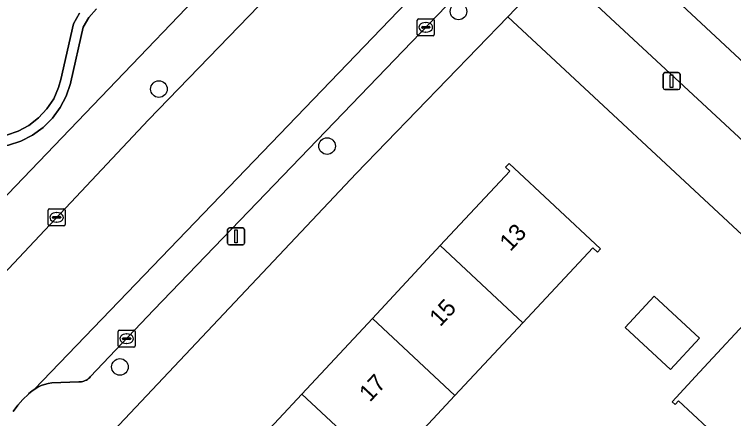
# Model space of a CAD drawing. Extents: x 159217 to 160349, y 381246 to 382172.
# Drawn here: x 159844.03 to 159886.39, y 381722 to 381745.8 of the extents above; entities that cross this region are included whole.
import ezdxf

# ---------------------------------------------------------------- set-up
doc = ezdxf.new("R2010")
doc.units = 0
for name, color, linetype in [('IMGEO_Boom', 7, 'Continuous'), ('IMGEO_Erf', 7, 'Continuous'), ('IMGEO_Groenvoorziening', 7, 'Continuous'), ('IMGEO_Haag', 7, 'Continuous'), ('IMGEO_Kolk', 7, 'Continuous'), ('IMGEO_Lichtmast', 7, 'Continuous'), ('IMGEO_Pand', 7, 'Continuous'), ('IMGEO_Pand_nummerreeks', 7, 'Continuous'), ('IMGEO_Parkeervlak_gesloten', 7, 'Continuous'), ('IMGEO_Rijbaan_lokaal_gesloten', 7, 'Continuous'), ('IMGEO_Voetpad_open', 7, 'Continuous')]:
    doc.layers.add(name, color=color, linetype=linetype)

msp = doc.modelspace()

# ---------------------------------------------------------------- linework, layer by layer
at = {"layer": 'IMGEO_Boom'}
for centre in [(159870.186, 381745.974), (159852.541, 381741.401), (159862.445, 381738.047), (159850.247, 381725.043)]:
    msp.add_circle(centre, 0.489, dxfattribs=at)
at = {"layer": 'IMGEO_Erf'}
for points in [[(159887.855, 381742.638), (159888.124, 381742.386), (159887.875, 381742.121), (159882.491, 381747.139), (159882.714, 381747.377), (159882.896, 381747.203), (159885.503, 381750), (159886.735, 381751.321), (159890.819, 381755.704), (159894.904, 381760.086), (159898.988, 381764.468), (159903.036, 381768.81), (159902.814, 381769.017), (159903.042, 381769.261), (159908.377, 381764.292), (159908.178, 381764.077), (159907.97, 381764.272), (159903.881, 381759.875), (159899.802, 381755.488), (159895.723, 381751.1), (159894.7, 381750), (159891.644, 381746.714)], [(159861.766, 381714.55), (159857.791, 381710.289), (159858.053, 381710.045), (159857.861, 381709.839), (159852.474, 381714.864), (159852.658, 381715.061), (159852.916, 381714.82), (159856.9, 381719.09), (159860.957, 381723.44), (159865.113, 381727.894), (159869.112, 381732.181), (159873.208, 381736.572), (159872.963, 381736.8), (159873.168, 381737.02), (159878.557, 381731.993), (159878.377, 381731.8), (159878.099, 381732.059), (159873.977, 381727.641), (159869.978, 381723.354), (159865.823, 381718.9)], [(159882.666, 381724.892), (159880.004, 381727.369), (159881.721, 381729.215), (159884.383, 381726.738)], [(159904.989, 381702.728), (159900.602, 381706.809), (159896.139, 381710.961), (159891.711, 381715.08), (159887.361, 381719.127), (159883.151, 381723.044), (159882.945, 381722.822), (159882.765, 381722.99), (159884.38, 381724.726), (159887.785, 381728.386), (159887.946, 381728.236), (159887.703, 381727.975), (159891.932, 381724.04), (159896.283, 381719.994), (159900.711, 381715.874), (159905.173, 381711.722), (159909.56, 381707.641), (159913.942, 381703.565), (159914.075, 381703.708), (159914.398, 381703.634), (159909.356, 381698.214), (159909.152, 381698.404), (159909.377, 381698.646), (159905.716, 381702.051)]]:
    msp.add_lwpolyline(points, close=True, dxfattribs=at)
for points in [[(159875.91, 381748.598), (159892.641, 381733.048), (159894.967, 381735.509), (159894.738, 381735.713), (159896.344, 381737.435), (159894.496, 381739.159), (159896.922, 381741.76), (159899.365, 381744.38), (159901.213, 381742.656), (159904.141, 381745.941)], [(159873.098, 381745.66), (159864.152, 381736.426), (159847.917, 381719.209), (159847.748, 381719.025), (159847.595, 381718.827), (159847.461, 381718.616), (159847.346, 381718.393), (159847.252, 381718.162), (159847.179, 381717.923), (159847.127, 381717.678), (159847.097, 381717.43), (159847.09, 381717.249)], [(159847.871, 381715.151), (159862.984, 381701.234), (159876.444, 381715.527), (159904.584, 381689.472), (159917.923, 381703.96), (159873.098, 381745.66)]]:
    msp.add_lwpolyline(points, dxfattribs=at)
at = {"layer": 'IMGEO_Groenvoorziening'}
for points in [[(159823.171, 381750), (159837.76, 381736.572), (159834.173, 381732.859), (159834.068, 381732.725), (159833.976, 381732.582), (159833.897, 381732.432), (159833.831, 381732.275), (159833.78, 381732.113), (159833.743, 381731.946), (159833.722, 381731.778), (159833.716, 381731.608), (159833.724, 381731.438), (159833.748, 381731.27), (159833.787, 381731.104), (159833.841, 381730.943), (159833.909, 381730.787), (159833.99, 381730.637), (159834.085, 381730.496), (159834.191, 381730.363), (159834.309, 381730.241), (159834.333, 381730.219), (159836.763, 381728.06), (159857.805, 381750)], [(159833.095, 381747.063), (159835.051, 381740.63), (159835.405, 381739.988), (159835.859, 381739.412), (159836.4, 381738.917), (159837.015, 381738.517), (159837.687, 381738.223), (159837.847, 381738.171), (159839.218, 381737.962), (159840.602, 381737.873), (159841.988, 381737.903), (159843.367, 381738.053), (159843.68, 381738.104), (159844.413, 381738.343), (159845.101, 381738.692), (159845.726, 381739.143), (159846.273, 381739.686), (159846.73, 381740.307), (159847.085, 381740.992), (159847.33, 381741.723), (159847.356, 381741.831), (159848.074, 381745.047), (159848.422, 381745.62), (159848.866, 381746.122)], [(159848.866, 381746.122), (159848.422, 381745.62), (159848.074, 381745.047), (159847.356, 381741.831), (159847.33, 381741.723), (159847.085, 381740.992), (159846.73, 381740.307), (159846.273, 381739.686), (159845.726, 381739.143), (159845.101, 381738.692), (159844.413, 381738.343), (159843.68, 381738.104), (159843.367, 381738.053), (159841.988, 381737.903), (159840.602, 381737.873), (159839.218, 381737.962), (159837.847, 381738.171), (159837.687, 381738.223), (159837.015, 381738.517), (159836.4, 381738.917), (159835.859, 381739.412), (159835.405, 381739.988), (159835.051, 381740.63), (159833.095, 381747.063)], [(159833.673, 381747.225), (159835.613, 381740.842), (159835.952, 381740.249), (159836.389, 381739.725), (159836.911, 381739.285), (159837.502, 381738.944), (159837.993, 381738.754), (159839.338, 381738.553), (159840.696, 381738.471), (159842.056, 381738.509), (159843.407, 381738.667), (159843.558, 381738.692), (159844.243, 381738.922), (159844.881, 381739.261), (159845.453, 381739.702), (159845.945, 381740.231), (159846.343, 381740.834), (159846.636, 381741.494), (159846.77, 381741.963), (159847.504, 381745.245), (159847.864, 381745.87)], [(159847.864, 381745.87), (159847.504, 381745.245), (159846.77, 381741.963), (159846.636, 381741.494), (159846.343, 381740.834), (159845.945, 381740.231), (159845.453, 381739.702), (159844.881, 381739.261), (159844.243, 381738.922), (159843.558, 381738.692), (159843.407, 381738.667), (159842.056, 381738.509), (159840.696, 381738.471), (159839.338, 381738.553), (159837.993, 381738.754), (159837.502, 381738.944), (159836.911, 381739.285), (159836.389, 381739.725), (159835.952, 381740.249), (159835.613, 381740.842), (159833.673, 381747.225)]]:
    msp.add_lwpolyline(points, dxfattribs=at)
at = {"layer": 'IMGEO_Haag'}
for points in [[(159833.095, 381747.063), (159835.051, 381740.63), (159835.405, 381739.988), (159835.859, 381739.412), (159836.4, 381738.917), (159837.015, 381738.517), (159837.687, 381738.223), (159837.847, 381738.171), (159839.218, 381737.962), (159840.602, 381737.873), (159841.988, 381737.903), (159843.367, 381738.053), (159843.68, 381738.104), (159844.413, 381738.343), (159845.101, 381738.692), (159845.726, 381739.143), (159846.273, 381739.686), (159846.73, 381740.307), (159847.085, 381740.992), (159847.33, 381741.723), (159847.356, 381741.831), (159848.074, 381745.047), (159848.422, 381745.62), (159848.866, 381746.122)], [(159847.864, 381745.87), (159847.504, 381745.245), (159846.77, 381741.963), (159846.636, 381741.494), (159846.343, 381740.834), (159845.945, 381740.231), (159845.453, 381739.702), (159844.881, 381739.261), (159844.243, 381738.922), (159843.558, 381738.692), (159843.407, 381738.667), (159842.056, 381738.509), (159840.696, 381738.471), (159839.338, 381738.553), (159837.993, 381738.754), (159837.502, 381738.944), (159836.911, 381739.285), (159836.389, 381739.725), (159835.952, 381740.249), (159835.613, 381740.842), (159833.673, 381747.225)]]:
    msp.add_lwpolyline(points, dxfattribs=at)
at = {"layer": 'IMGEO_Kolk'}
for p, q in [((159867.76, 381744.611), (159867.76, 381745.463)), ((159867.835, 381745.537), (159868.687, 381745.537)), ((159868.248, 381745.317), (159868.273, 381745.317)), ((159868.761, 381745.463), (159868.761, 381744.611)), ((159868.019, 381745.031), (159868.019, 381745.043)), ((159868.457, 381744.994), (159868.059, 381744.994)), ((159868.062, 381745.08), (159868.46, 381745.08)), ((159868.503, 381745.043), (159868.503, 381745.031)), ((159868.687, 381744.537), (159867.835, 381744.537)), ((159868.271, 381744.757), (159868.246, 381744.757)), ((159846.015, 381733.422), (159846.015, 381734.274)), ((159846.09, 381734.348), (159846.942, 381734.348)), ((159847.016, 381734.274), (159847.016, 381733.422)), ((159846.274, 381733.842), (159846.274, 381733.854)), ((159846.712, 381733.805), (159846.314, 381733.805)), ((159846.317, 381733.891), (159846.715, 381733.891)), ((159846.503, 381734.128), (159846.528, 381734.128)), ((159846.758, 381733.854), (159846.758, 381733.842)), ((159846.526, 381733.568), (159846.501, 381733.568)), ((159846.942, 381733.348), (159846.09, 381733.348)), ((159850.139, 381726.279), (159850.139, 381727.131)), ((159850.214, 381727.205), (159851.066, 381727.205)), ((159851.14, 381727.131), (159851.14, 381726.279)), ((159850.398, 381726.699), (159850.398, 381726.711)), ((159850.836, 381726.662), (159850.438, 381726.662)), ((159850.441, 381726.748), (159850.839, 381726.748)), ((159850.627, 381726.985), (159850.652, 381726.985)), ((159850.882, 381726.711), (159850.882, 381726.699)), ((159851.066, 381726.205), (159850.214, 381726.205)), ((159850.65, 381726.425), (159850.625, 381726.425))]:
    msp.add_line(p, q, dxfattribs=at)
for points in [[(159867.76, 381744.611), (159867.76, 381745.463)], [(159867.835, 381745.537), (159868.687, 381745.537)], [(159868.761, 381745.463), (159868.761, 381744.611)], [(159868.687, 381744.537), (159867.835, 381744.537)], [(159846.015, 381733.422), (159846.015, 381734.274)], [(159846.09, 381734.348), (159846.942, 381734.348)], [(159847.016, 381734.274), (159847.016, 381733.422)], [(159846.942, 381733.348), (159846.09, 381733.348)], [(159850.139, 381726.279), (159850.139, 381727.131)], [(159850.214, 381727.205), (159851.066, 381727.205)], [(159851.14, 381727.131), (159851.14, 381726.279)], [(159851.066, 381726.205), (159850.214, 381726.205)]]:
    msp.add_lwpolyline(points, dxfattribs=at)
for centre, radius, start, end in [((159867.837, 381745.461), 0.0765, 91.552, 178.448), ((159867.837, 381745.461), 0.0765, 91.552, 178.448), ((159868.685, 381745.461), 0.0765, 1.552, 88.448), ((159868.685, 381745.461), 0.0765, 1.552, 88.448), ((159868.059, 381745.04), 0.0403, 85.8775, 175.7526), ((159868.056, 381745.03), 0.0366, 178.938, 274.7102), ((159868.46, 381745.037), 0.043, 264.8664, 352.4533), ((159868.464, 381745.042), 0.0386, 1.7309, 96.639), ((159867.837, 381744.613), 0.0765, 181.552, 268.448), ((159867.837, 381744.613), 0.0765, 181.552, 268.448), ((159868.685, 381744.613), 0.0765, 271.552, 358.448), ((159868.685, 381744.613), 0.0765, 271.552, 358.448), ((159846.092, 381734.272), 0.0765, 91.552, 178.448), ((159846.092, 381734.272), 0.0765, 91.552, 178.448), ((159846.94, 381734.272), 0.0765, 1.552, 88.448), ((159846.94, 381734.272), 0.0765, 1.552, 88.448), ((159846.314, 381733.851), 0.0403, 85.8775, 175.7526), ((159846.311, 381733.841), 0.0366, 178.938, 274.7102), ((159846.715, 381733.848), 0.043, 264.8664, 352.4533), ((159846.719, 381733.853), 0.0386, 1.7309, 96.639), ((159846.092, 381733.424), 0.0765, 181.552, 268.448), ((159846.092, 381733.424), 0.0765, 181.552, 268.448), ((159846.94, 381733.424), 0.0765, 271.552, 358.448), ((159846.94, 381733.424), 0.0765, 271.552, 358.448), ((159850.216, 381727.129), 0.0765, 91.552, 178.448), ((159850.216, 381727.129), 0.0765, 91.552, 178.448), ((159851.064, 381727.129), 0.0765, 1.552, 88.448), ((159851.064, 381727.129), 0.0765, 1.552, 88.448), ((159850.438, 381726.708), 0.0403, 85.8775, 175.7526), ((159850.435, 381726.698), 0.0366, 178.938, 274.7102), ((159850.839, 381726.705), 0.043, 264.8664, 352.4533), ((159850.843, 381726.71), 0.0386, 1.7309, 96.639), ((159850.216, 381726.281), 0.0765, 181.552, 268.448), ((159850.216, 381726.281), 0.0765, 181.552, 268.448), ((159851.064, 381726.281), 0.0765, 271.552, 358.448), ((159851.064, 381726.281), 0.0765, 271.552, 358.448)]:
    msp.add_arc(centre, radius, start, end, dxfattribs=at)
for centre, major_axis, ratio, start_param, end_param in [((159868.247, 381745.037), (-0.387, 0.002), 0.722429, 4.712389, 7.853982), ((159868.272, 381745.037), (-0.39, 0.002), 0.717154, 1.570796, 4.712389), ((159846.502, 381733.848), (-0.387, 0.002), 0.722429, 4.712389, 7.853982), ((159846.527, 381733.848), (-0.39, 0.002), 0.717154, 1.570796, 4.712389), ((159850.626, 381726.705), (-0.387, 0.002), 0.722429, 4.712389, 7.853982), ((159850.651, 381726.705), (-0.39, 0.002), 0.717154, 1.570796, 4.712389)]:
    msp.add_ellipse(centre, major_axis=major_axis, ratio=ratio, start_param=start_param, end_param=end_param, dxfattribs=at)
at = {"layer": 'IMGEO_Lichtmast'}
for p, q in [((159882.344, 381742.37), (159883.134, 381742.37)), ((159883.134, 381742.37), (159882.344, 381742.37)), ((159882.244, 381741.47), (159882.244, 381742.27)), ((159882.244, 381742.27), (159882.244, 381741.47)), ((159883.234, 381742.27), (159883.234, 381741.47)), ((159883.234, 381741.47), (159883.234, 381742.27)), ((159883.134, 381741.37), (159882.344, 381741.37)), ((159882.344, 381741.37), (159883.134, 381741.37)), ((159856.59, 381732.329), (159856.59, 381733.129)), ((159856.59, 381733.129), (159856.59, 381732.329)), ((159856.69, 381733.229), (159857.48, 381733.229)), ((159857.48, 381733.229), (159856.69, 381733.229)), ((159857.58, 381733.129), (159857.58, 381732.329)), ((159857.58, 381732.329), (159857.58, 381733.129)), ((159857.48, 381732.229), (159856.69, 381732.229)), ((159856.69, 381732.229), (159857.48, 381732.229))]:
    msp.add_line(p, q, dxfattribs=at)
for points in [[(159882.664, 381742.245), (159882.814, 381742.245), (159882.814, 381741.495), (159882.664, 381741.495), (159882.664, 381742.245)], [(159857.01, 381733.104), (159857.16, 381733.104), (159857.16, 381732.354), (159857.01, 381732.354), (159857.01, 381733.104)]]:
    msp.add_lwpolyline(points, dxfattribs=at)
for centre, start, end in [((159882.344, 381742.27), 90, 180), ((159882.344, 381742.27), 90, 180), ((159883.134, 381742.27), 0, 90), ((159883.134, 381742.27), 360, 90), ((159882.344, 381741.47), 180, 270), ((159882.344, 381741.47), 180, 270), ((159883.134, 381741.47), 270, 0), ((159883.134, 381741.47), 270, 0), ((159856.69, 381733.129), 90, 180), ((159856.69, 381733.129), 90, 180), ((159857.48, 381733.129), 0, 90), ((159857.48, 381733.129), 360, 90), ((159856.69, 381732.329), 180, 270), ((159856.69, 381732.329), 180, 270), ((159857.48, 381732.329), 270, 0), ((159857.48, 381732.329), 270, 0)]:
    msp.add_arc(centre, 0.1, start, end, dxfattribs=at)
at = {"layer": 'IMGEO_Pand'}
for points in [[(159891.644, 381746.714), (159888.143, 381750), (159886.735, 381751.321), (159885.503, 381750), (159882.896, 381747.203), (159882.714, 381747.377), (159882.491, 381747.139), (159887.875, 381742.121), (159888.124, 381742.386), (159887.855, 381742.638)], [(159869.112, 381732.181), (159873.977, 381727.641), (159878.099, 381732.059), (159878.377, 381731.8), (159878.557, 381731.993), (159873.168, 381737.02), (159872.963, 381736.8), (159873.208, 381736.572)], [(159865.113, 381727.894), (159869.978, 381723.354), (159873.977, 381727.641), (159869.112, 381732.181)], [(159882.666, 381724.892), (159884.383, 381726.738), (159881.721, 381729.215), (159880.004, 381727.369)], [(159891.932, 381724.04), (159887.703, 381727.975), (159887.946, 381728.236), (159887.785, 381728.386), (159884.38, 381724.726), (159882.765, 381722.99), (159882.945, 381722.822), (159883.151, 381723.044), (159887.361, 381719.127)], [(159865.823, 381718.9), (159869.978, 381723.354), (159865.113, 381727.894), (159860.957, 381723.44)], [(159865.823, 381718.9), (159860.957, 381723.44), (159856.9, 381719.09), (159861.766, 381714.55)]]:
    msp.add_lwpolyline(points, close=True, dxfattribs=at)
at = {"layer": 'IMGEO_Parkeervlak_gesloten'}
msp.add_lwpolyline([(159847.832, 381724.164), (159847.907, 381724.165), (159847.982, 381724.172), (159848.057, 381724.186), (159848.129, 381724.207), (159848.2, 381724.234), (159848.267, 381724.267), (159848.332, 381724.306), (159848.392, 381724.351), (159848.449, 381724.401), (159848.501, 381724.456), (159852.249, 381728.402), (159873.006, 381750), (159885.44, 381762.927), (159887.03, 381764.51), (159888.904, 381766.453), (159887.563, 381767.762), (159845.193, 381723.719), (159845.224, 381723.741), (159845.41, 381723.85), (159845.604, 381723.942), (159845.806, 381724.016), (159846.014, 381724.072), (159846.226, 381724.109)], close=True, dxfattribs=at)
at = {"layer": 'IMGEO_Rijbaan_lokaal_gesloten'}
for points in [[(159843.96, 381722.423), (159844.228, 381722.791), (159844.527, 381723.133), (159844.856, 381723.447), (159844.886, 381723.476), (159845.049, 381723.616), (159845.193, 381723.719), (159887.563, 381767.762)], [(159861.976, 381750), (159851.927, 381739.596), (159839.079, 381725.943), (159835.884, 381722.548), (159820.61, 381706.317), (159819.093, 381704.705)]]:
    msp.add_lwpolyline(points, dxfattribs=at)
at = {"layer": 'IMGEO_Voetpad_open'}
for points in [[(159857.805, 381750), (159836.763, 381728.06), (159836.342, 381727.662), (159834.247, 381725.568), (159827.45, 381718.318), (159820.214, 381710.509), (159817.766, 381707.849)], [(159819.093, 381704.705), (159820.61, 381706.317), (159835.884, 381722.548), (159839.079, 381725.943), (159851.927, 381739.596), (159861.976, 381750)], [(159873.006, 381750), (159852.249, 381728.402), (159848.501, 381724.456), (159848.449, 381724.401), (159848.392, 381724.351), (159848.332, 381724.306), (159848.267, 381724.267), (159848.2, 381724.234), (159848.129, 381724.207), (159848.057, 381724.186), (159847.982, 381724.172), (159847.907, 381724.165), (159847.832, 381724.164), (159846.226, 381724.109), (159846.014, 381724.072), (159845.806, 381724.016), (159845.604, 381723.942), (159845.41, 381723.85), (159845.224, 381723.741), (159845.193, 381723.719), (159845.049, 381723.616), (159844.886, 381723.476), (159844.856, 381723.447), (159844.527, 381723.133), (159844.228, 381722.791), (159843.96, 381722.423)], [(159843.959, 381717.031), (159844.247, 381716.643), (159844.568, 381716.282), (159844.822, 381716.038), (159847.595, 381718.827), (159847.748, 381719.025), (159847.917, 381719.209), (159864.152, 381736.426), (159873.098, 381745.66), (159875.91, 381748.598)], [(159892.641, 381733.048), (159875.91, 381748.598), (159873.098, 381745.66), (159917.923, 381703.96)]]:
    msp.add_lwpolyline(points, dxfattribs=at)

# ---------------------------------------------------------------- texts
at = {"layer": 'IMGEO_Pand_nummerreeks'}
for s, p in [('13', (159873.242, 381731.801)), ('15', (159869.106, 381727.367)), ('17', (159864.97, 381722.933))]:
    msp.add_text(s, height=1, rotation=46.9889, dxfattribs=at).set_placement(p)

doc.saveas('drawing.dxf')
